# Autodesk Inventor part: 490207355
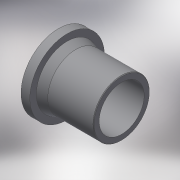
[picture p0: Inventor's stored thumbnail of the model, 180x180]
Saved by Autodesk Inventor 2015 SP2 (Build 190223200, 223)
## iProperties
Created: 2017-07
Part Number: 490207355
Material: Generic
Description: Stub Flange 355
Document SubType Name: Modeling
Designer: Кирилл
Mass: 11050.5 g
Surface Area: 6980.05 cm^2
Volume: 11050.5 cm^3
Density: 1 g/cm^3
Appearance: Default
Author: Кирилл
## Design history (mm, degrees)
derived "490207.ipt"
feature "Solid1::490207.ipt"
tag "TaggingFeature1"
body "Solid1"
other parameters: "d0" = 255, "d1" = 373, "d2" = 355, "d3" = 284, "d6" = 175, "d16" = 355, "d17" = 7.1, "d18" = 7.1, "d19" = 7.1, "d21" = 7.1, "d24" = 7.1, "d25" = 7.1, "d26" = 3.55, "d27" = 0, "d32" = 3.55, "d_" = 355, "L_" = 255, "L_1" = 175, "D_1" = 373
